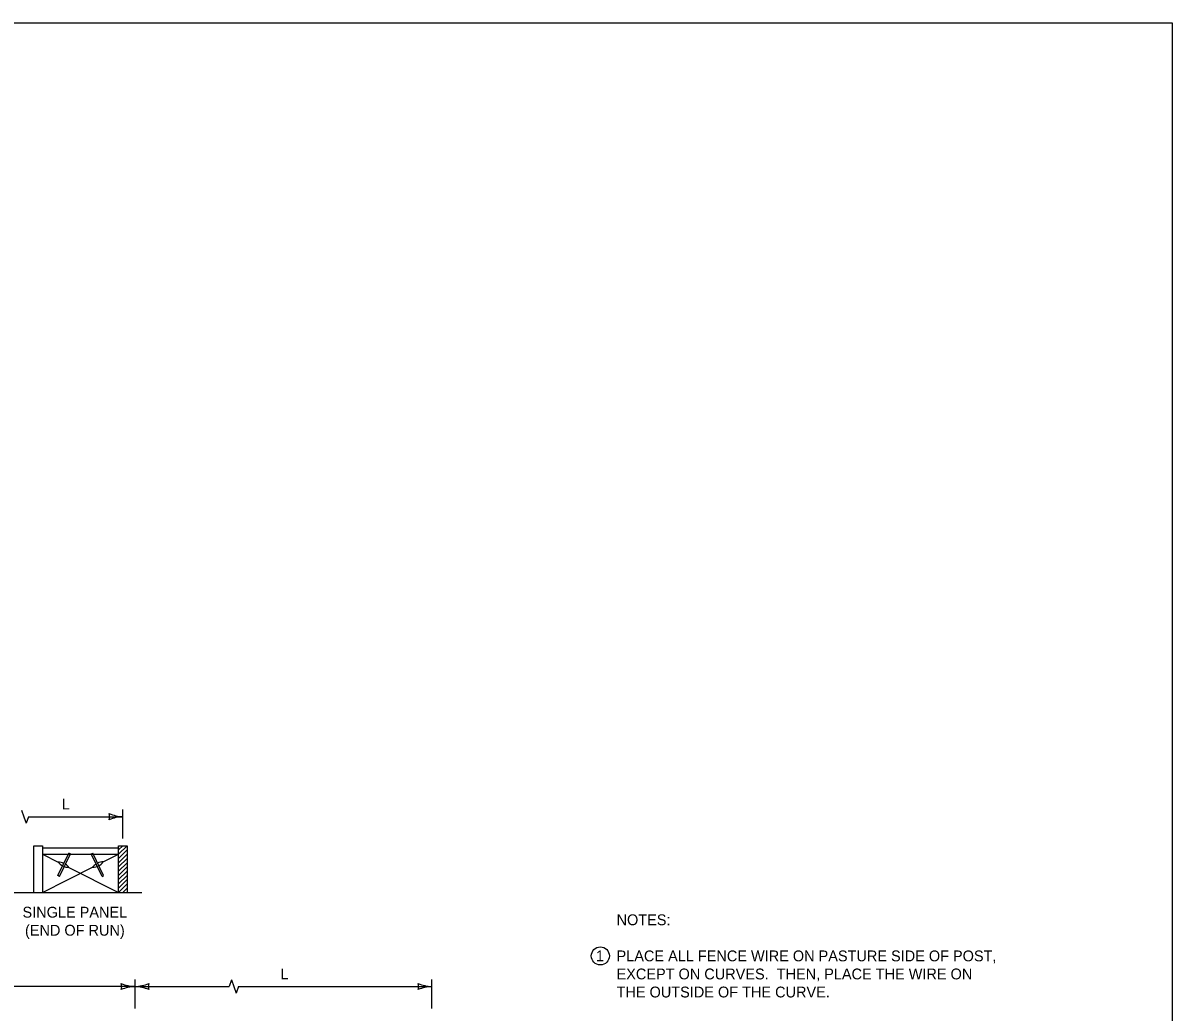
# Model space of a CAD drawing. Extents: x 49991.4 to 50021, y 49987.6 to 50011.4.
# Drawn here: x 50010.39 to 50016.75, y 49993.52 to 49999 of the extents above; entities that cross this region are included whole.
import ezdxf

# ---------------------------------------------------------------- set-up
doc = ezdxf.new("R2010")
doc.units = 0
for name, color, linetype in [('Level 1', 7, 'Continuous'), ('Level 2', 7, 'Continuous'), ('Level 3', 7, 'Continuous')]:
    doc.layers.add(name, color=color, linetype=linetype)

msp = doc.modelspace()

# ---------------------------------------------------------------- linework, layer by layer
at = {"layer": 'Level 1'}
for p, q in [((50010.4457, 49994.1848), (50010.4457, 49994.4431)), ((50010.4457, 49994.4431), (50010.4926, 49994.4431)), ((50010.4926, 49994.4431), (50010.4926, 49994.1848)), ((50010.4926, 49994.4313), (50010.9152, 49994.4313)), ((50010.9152, 49994.1848), (50010.9152, 49994.4431)), ((50010.9152, 49994.4431), (50010.9622, 49994.4431)), ((50010.9152, 49994.3961), (50010.9622, 49994.4431)), ((50010.9152, 49994.4195), (50010.9387, 49994.4431)), ((50010.9622, 49994.4431), (50010.9622, 49994.1848)), ((50010.4926, 49994.3961), (50010.9152, 49994.3961)), ((50010.4926, 49994.3961), (50010.5802, 49994.3523)), ((50010.5786, 49994.2777), (50010.6393, 49994.4019)), ((50010.5873, 49994.2733), (50010.6484, 49994.3973)), ((50010.6484, 49994.3973), (50010.6393, 49994.4019)), ((50010.7622, 49994.3973), (50010.7714, 49994.4019)), ((50010.8233, 49994.2732), (50010.7622, 49994.3973)), ((50010.832, 49994.2776), (50010.7714, 49994.4019)), ((50010.8299, 49994.3534), (50010.9152, 49994.3961)), ((50010.9152, 49994.3726), (50010.9622, 49994.4195)), ((50010.9152, 49994.3491), (50010.9622, 49994.3961)), ((50010.9152, 49994.3257), (50010.9622, 49994.3726)), ((50010.4926, 49994.1848), (50010.771, 49994.3244)), ((50010.639, 49994.3233), (50010.9152, 49994.1848)), ((50010.9152, 49994.3021), (50010.9622, 49994.3491)), ((50010.9152, 49994.2787), (50010.9622, 49994.3257)), ((50010.9152, 49994.2553), (50010.9622, 49994.3021)), ((50010.5873, 49994.2733), (50010.5786, 49994.2777)), ((50010.8233, 49994.2732), (50010.832, 49994.2776)), ((50010.9152, 49994.2317), (50010.9622, 49994.2787)), ((50010.9152, 49994.2083), (50010.9622, 49994.2553)), ((50008.0157, 49994.1848), (50011.0438, 49994.1848)), ((50010.9152, 49994.1848), (50010.9622, 49994.2317)), ((50010.9387, 49994.1848), (50010.9622, 49994.2083))]:
    msp.add_line(p, q, dxfattribs=at)
msp.add_lwpolyline([(49999.3835, 49998.9992), (50016.7501, 49998.9992), (50016.7501, 49987.7988), (49999.3835, 49987.7988)], close=True, dxfattribs=at)
for centre, start, end in [((50010.6383, 49994.3961), 216.97154, 270.55889), ((50010.5809, 49994.2795), 64.93198, 90.55889), ((50010.5809, 49994.2795), 36.97154, 57.05605), ((50010.7717, 49994.3972), 269.44111, 323.02846), ((50010.8292, 49994.2806), 122.9506, 143.02846), ((50010.8292, 49994.2806), 89.44111, 115.05261)]:
    msp.add_arc(centre, 0.0728, start, end, dxfattribs=at)
at = {"layer": 'Level 2'}
msp.add_circle((50013.5833, 49993.8328), 0.05, dxfattribs=at)
at = {"layer": 'Level 3'}
for p, q in [((50010.3775, 49994.6405), (50010.3904, 49994.6039)), ((50010.9381, 49994.4831), (50010.9381, 49994.644)), ((50010.3904, 49994.6039), (50010.4034, 49994.5673)), ((50010.4163, 49994.6039), (50010.4034, 49994.5673)), ((50010.4163, 49994.6039), (50010.9381, 49994.6039)), ((50011.0056, 49993.703), (50011.0056, 49993.5421)), ((50011.5404, 49993.6996), (50011.5274, 49993.663)), ((50011.5404, 49993.6996), (50011.5533, 49993.663)), ((50012.6498, 49993.5421), (50012.6498, 49993.703)), ((50011.0056, 49993.663), (50009.9348, 49993.663)), ((50011.0056, 49993.663), (50011.5274, 49993.663)), ((50011.5533, 49993.663), (50011.5663, 49993.6265)), ((50011.5792, 49993.663), (50011.5663, 49993.6265)), ((50011.5792, 49993.663), (50012.6498, 49993.663))]:
    msp.add_line(p, q, dxfattribs=at)
for centre, radius, start, end in [((50010.9473, 49994.8261), 0.2223, 247.45601, 267.63952), ((50010.8099, 49994.6039), 0.0548, 342.13882, 17.86118), ((50010.9496, 49994.3712), 0.233, 92.82731, 112.07716), ((50011.0148, 49993.8851), 0.2223, 247.45601, 267.63952), ((50010.8774, 49993.663), 0.0548, 342.13882, 17.86118), ((50010.9941, 49993.8957), 0.233, 272.82731, 292.07716), ((50011.1338, 49993.663), 0.0548, 162.13882, 197.86118), ((50012.659, 49993.8851), 0.2223, 247.45601, 267.63952), ((50012.5216, 49993.663), 0.0548, 342.13882, 17.86118), ((50011.0171, 49993.4303), 0.233, 92.82731, 112.07716), ((50010.9965, 49993.4408), 0.2223, 67.45601, 87.63952), ((50012.6613, 49993.4303), 0.233, 92.82731, 112.07716)]:
    msp.add_arc(centre, radius, start, end, dxfattribs=at)

# ---------------------------------------------------------------- texts
at = {"layer": 'Level 2'}
for s, p in [('L', (50010.5995, 49994.644)), ('SINGLE PANEL', (50010.3827, 49994.0448)), ('NOTES:', (50013.6733, 49994.0028)), ('(END OF RUN)', (50010.3963, 49993.9448)), ('1', (50013.5588, 49993.8028)), ('PLACE ALL FENCE WIRE ON PASTURE SIDE OF POST,', (50013.6733, 49993.8028)), ('L', (50011.8107, 49993.703)), ('EXCEPT ON CURVES.  THEN, PLACE THE WIRE ON', (50013.6733, 49993.7028)), ('THE OUTSIDE OF THE CURVE.', (50013.6733, 49993.6028))]:
    msp.add_text(s, height=0.06, dxfattribs=at).set_placement(p)

doc.saveas('drawing.dxf')
